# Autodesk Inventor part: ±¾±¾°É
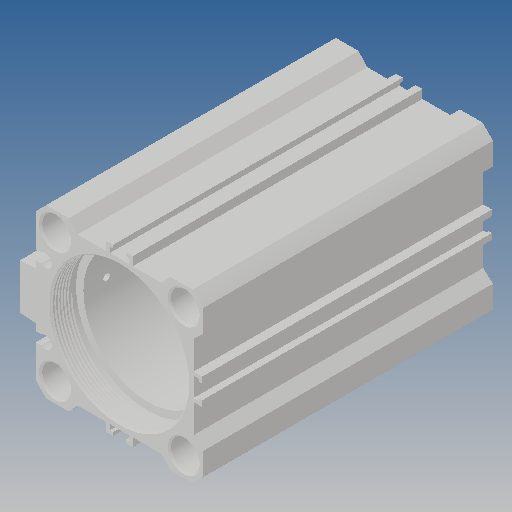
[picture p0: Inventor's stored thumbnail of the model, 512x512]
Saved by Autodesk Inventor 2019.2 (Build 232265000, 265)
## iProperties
Created: 2013-09
Part Number: ±¾±¾°É
Material: Ogólny
Document SubType Name: Modeling
Designer: CADENGINEERING4
Density: 1 g/cm^3
Appearance: Domyślna
Author: CADENGINEERING4
Revision Number: ÈÎºÎ
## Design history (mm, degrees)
feature "¾µÏò1"
node "Bryła1"
